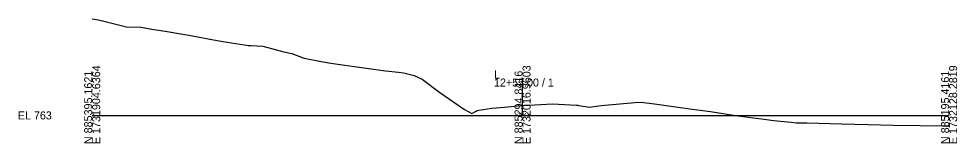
# Model space of a CAD drawing. Extents: x -173 to 6803, y -2990 to 11029.
# Drawn here: x 3874.3 to 4202.7, y -9.7 to 33.7 of the extents above; entities that cross this region are included whole.
import ezdxf

# ---------------------------------------------------------------- set-up
doc = ezdxf.new("R2010")
doc.units = 0
for name, color, linetype in [('Default', 7, 'Continuous'), ('Exist Cross Section Cell', 7, 'Continuous'), ('Exist XS Center Line Elevation Label', 7, 'Continuous'), ('Exist XS Ground Line', 7, 'Continuous')]:
    doc.layers.add(name, color=color, linetype=linetype)

msp = doc.modelspace()

# ---------------------------------------------------------------- linework, layer by layer
at = {"layer": 'Exist Cross Section Cell'}
for p, q in [((4050.6, 0), (4050.6, 12.88)), ((3900, 0), (4050.6, 0)), ((4050.6, 0), (4199.86, 0))]:
    msp.add_line(p, q, dxfattribs=at)
at = {"layer": 'Exist XS Ground Line'}
msp.add_lwpolyline([(3900, 33.72), (3901.55, 33.53), (3903.19, 33.17), (3912.05, 30.87), (3917.17, 30.81), (3920.82, 30.13), (3925.48, 29.45), (3927.63, 29.06), (3929.6, 28.76), (3933.85, 28.05), (3943.78, 26.19), (3947.18, 25.59), (3953.32, 24.64), (3954.61, 24.38), (3955.5, 24.35), (3959.76, 24.14), (3967.11, 22.16), (3969.84, 21.57), (3973.82, 20.12), (3974.23, 19.93), (3980.16, 18.8), (3983.54, 18.26), (3986.79, 17.74), (4002.67, 15.53), (4007.22, 15.15), (4008.91, 14.88), (4012.65, 13.94), (4015.44, 12.7), (4021.64, 8.05), (4030.29, 2.05), (4032.8, 0.71), (4034.17, 1.41), (4034.73, 1.72), (4035.32, 1.79), (4039.82, 2.5), (4044.31, 2.89), (4050.07, 3.41), (4050.6, 3.44), (4054.93, 3.69), (4061.11, 4.06), (4069.44, 3.57), (4069.77, 3.55), (4070.17, 3.49), (4074.07, 2.89), (4078.15, 3.44), (4089.87, 4.48), (4091.94, 4.64), (4096.79, 4.03), (4109.18, 2.35), (4116.31, 1.39), (4125.88, -0.1), (4135.13, -1.27), (4138.44, -1.77), (4144.56, -2.4), (4146.46, -2.59), (4150.12, -2.61), (4162.15, -2.9), (4171.51, -3.13), (4180.26, -3.35), (4189.77, -3.52), (4198.06, -3.66), (4199.86, -3.69)], dxfattribs=at)

# ---------------------------------------------------------------- texts
at = {"layer": 'Default'}
msp.add_text('-', height=0.0001, dxfattribs=at).set_placement((3900, 0))
at = {"layer": 'Exist Cross Section Cell'}
for s, p in [('E 1731904.6364', (3902.8, -10)), ('E 1732016.9603', (4053.4, -10)), ('E 1732128.2819', (4202.66, -10)), ('N 885395.1621', (3900, -10)), ('N 885294.8416', (4050.6, -10)), ('N 885195.4161', (4199.86, -10))]:
    msp.add_text(s, height=2.8, rotation=90, dxfattribs=at).set_placement(p)
for s, p in [('L', (4040.6, 12.88)), ('12+55.00 / 1', (4040.6, 10.08)), ('EL 763', (3874, -1.4))]:
    msp.add_text(s, height=2.8, dxfattribs=at).set_placement(p)
at = {"layer": 'Exist XS Center Line Elevation Label'}
msp.add_text('766.44', height=1, rotation=360, dxfattribs=at).set_placement((4048.55, -0.01))

doc.saveas('drawing.dxf')
